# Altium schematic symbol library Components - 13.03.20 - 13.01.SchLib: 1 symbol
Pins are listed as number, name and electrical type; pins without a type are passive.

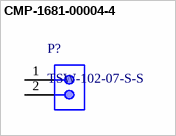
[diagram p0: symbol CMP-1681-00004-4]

## CMP-1681-00004-4
designator P?, comment TSW-102-07-S-S
Male Header, Pitch 2.54 mm, 1 x 2 Position, Height 8.38 mm, Tail Length 2.54 mm, -55 to 125 degC, RoHS, Bulk; Manufacturer: Samtec; Rows: 1
footprint SMTC-TSW-102-07-S-S (Header, 2-Leads, Body 5.08x2.54mm, Pitch 2.54mm)
pins: 1, 2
